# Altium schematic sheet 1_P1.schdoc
size 309 x 223 mm; Symbol: Sheet-Symbol_A4; Device: Sheet-Symbol_A4; Company: 嘉立创EDA; Version: V1.0; Page Size: A4; @Project Name: 电动车中控1; @Page Count: 11; @Update Date: 2024-10-22; @Create Date: 2024-09-26; @Schematic Name: SCH; @Page No: 1; @Page Name: P1; Title Block Position: 3; Width: 1170; Height: 825; Region Start: 1; X Region Count: 6; Y Region Count: 4; Blade Width: 10; @Board Name: STM32F103C8T6; @Create Time: 02:39:01; @Update Time: 14:42:37
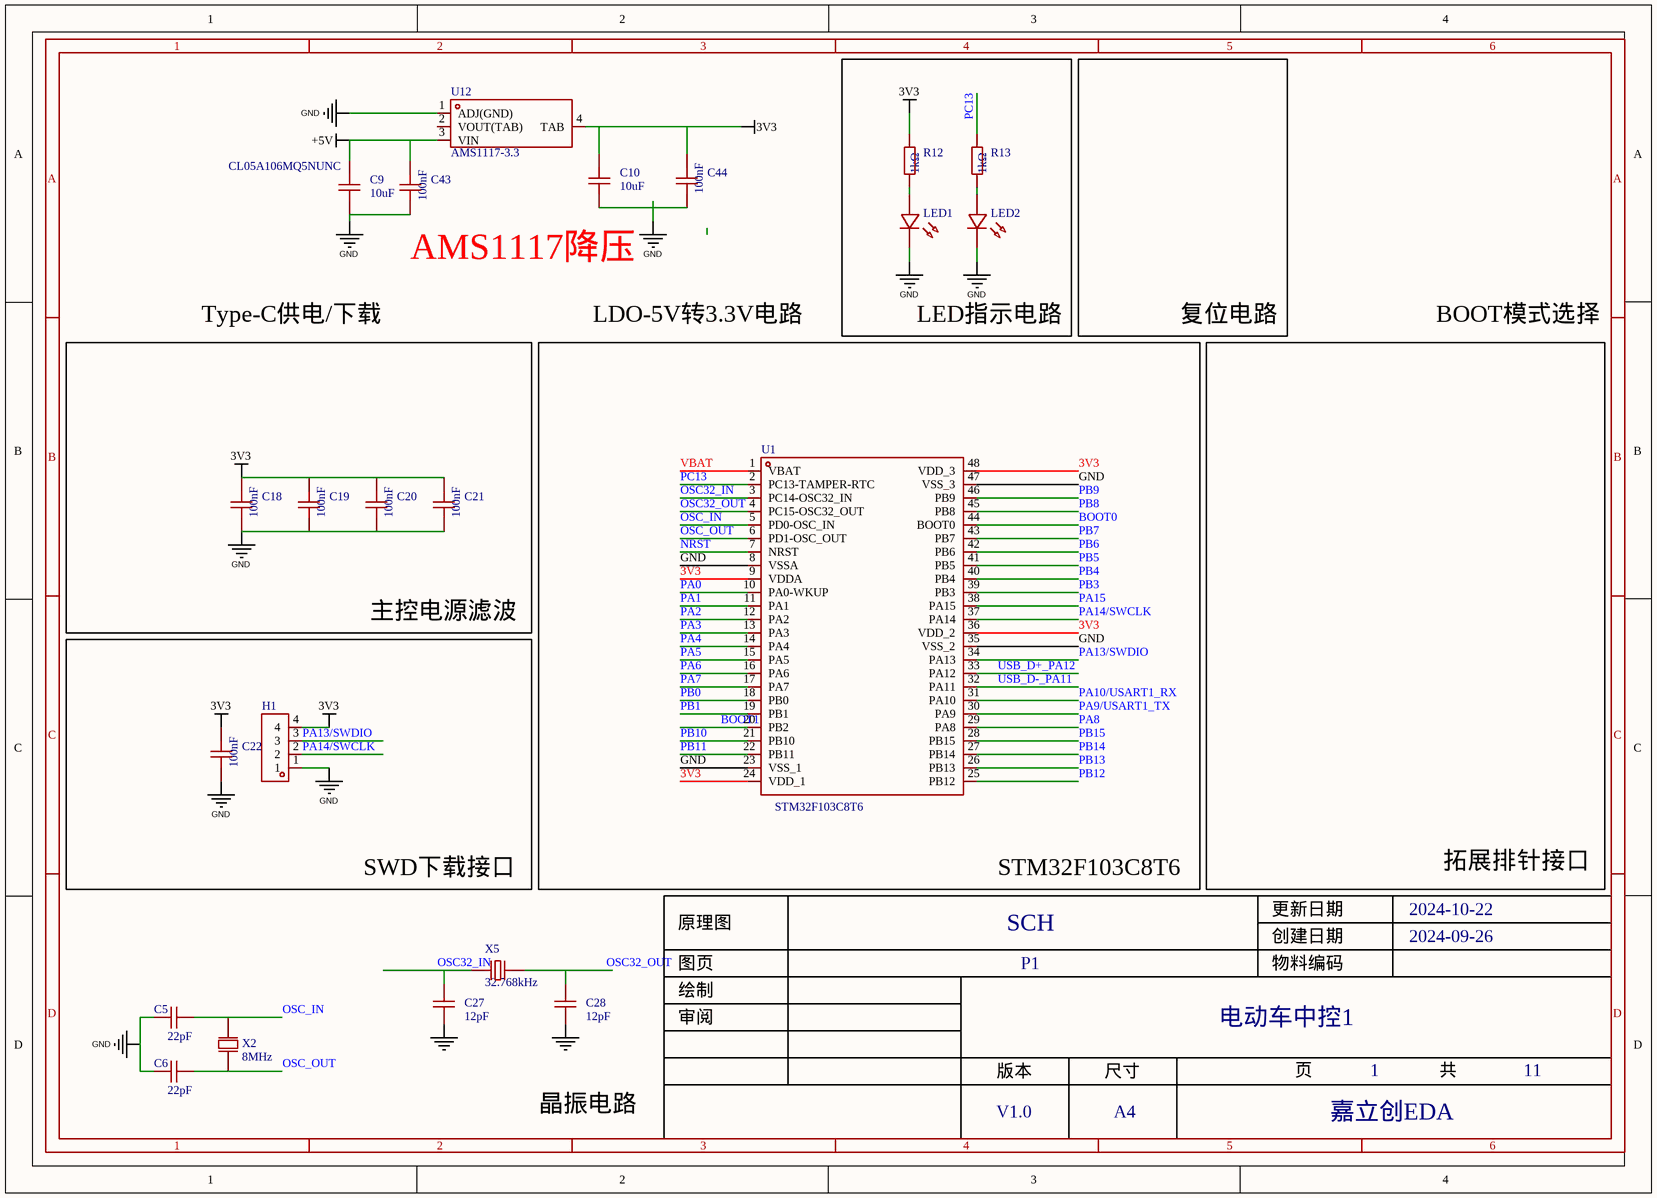
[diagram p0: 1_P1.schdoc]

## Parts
C5  22pF  [C0603]  (value not drawn)
C6  22pF  [C0603]  (value not drawn)
C9  10uF  [C0402]  (value not drawn)
C10  10uF  [C0402]  (value not drawn)
C18  100nF  [C0805]
C19  100nF  [C0805]
C20  100nF  [C0805]
C21  100nF  [C0805]
C22  100nF  [C0805]
C27  12pF  [C0805]
C28  12pF  [C0805]
C43  100nF  [C0805]
C44  100nF  [C0805]
H1  HDR-M_2.54_1x4P  [HDR-TH_4P-P2.54-V-M]  (value not drawn)
LED1  NCD0805R1  [LED0805-R-RD]  (value not drawn)
LED2  KT-0805G  [LED0805-R-RD]  (value not drawn)
R12  1kΩ  [R0805]
R13  1kΩ  [R0805]
U1  STM32F103C8T6  [LQFP-48_L7.0-W7.0-P0.50-LS9.0-BL]
U12  AMS1117-3.3  [SOT-223-3_L6.5-W3.4-P2.30-LS7.0-BR]  (value not drawn)
X2  8MHz  [CRYSTAL-SMD_L11.5-W4.8-LS12.7]  (value not drawn)
X5  32.768kHz  [FC-135R_L3.2-W1.5]

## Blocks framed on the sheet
LED指示电路: LED1 LED2 R12 R13

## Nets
3V3: C10.2 C18.2 C19.2 C20.2 C21.2 C22.2 C44.2 H1.4 R12.2 U1.9(VDDA) U1.24(VDD_1) U1.36(VDD_2) U1.48(VDD_3) U12.4(TAB)
+5V: C9.2 C43.2 U12.3(VIN)
GND: C5.1 C6.1 C9.1 C10.1 C18.1 C19.1 C20.1 C21.1 C22.1 C27.1 C28.1 C43.1 C44.1 H1.1 LED1.1(C) LED2.1(C) U1.8(VSSA) U1.23(VSS_1) U1.35(VSS_2) U1.47(VSS_3) U12.1(ADJ(GND))
BOOT0: U1.44(BOOT0)
BOOT1: U1.20(PB2)
NRST: U1.7(NRST)
OSC32_IN: C27.2 U1.3(PC14-OSC32_IN) X5.1
OSC32_OUT: C28.2 U1.4(PC15-OSC32_OUT) X5.2
OSC_IN: C5.2 U1.5(PD0-OSC_IN) X2.2
OSC_OUT: C6.2 U1.6(PD1-OSC_OUT) X2.1
PA0: U1.10(PA0-WKUP)
PA1: U1.11(PA1)
PA2: U1.12(PA2)
PA3: U1.13(PA3)
PA4: U1.14(PA4)
PA5: U1.15(PA5)
PA6: U1.16(PA6)
PA7: U1.17(PA7)
PA8: U1.29(PA8)
PA9/USART1_TX: U1.30(PA9)
PA10/USART1_RX: U1.31(PA10)
PA13/SWDIO: H1.3 U1.34(PA13)
PA14/SWCLK: H1.2 U1.37(PA14)
PA15: U1.38(PA15)
PB0: U1.18(PB0)
PB1: U1.19(PB1)
PB3: U1.39(PB3)
PB4: U1.40(PB4)
PB5: U1.41(PB5)
PB6: U1.42(PB6)
PB7: U1.43(PB7)
PB8: U1.45(PB8)
PB9: U1.46(PB9)
PB10: U1.21(PB10)
PB11: U1.22(PB11)
PB12: U1.25(PB12)
PB13: U1.26(PB13)
PB14: U1.27(PB14)
PB15: U1.28(PB15)
PC13: R13.2 U1.2(PC13-TAMPER-RTC)
USB_D+_PA12: U1.33(PA12)
USB_D-_PA11: U1.32(PA11)
VBAT: U1.1(VBAT)
NetLED1_2: LED1.2(A) R12.1
NetLED2_2: LED2.2(A) R13.1

Not connected (* = marked no-connect by the designer): U12 2(VOUT(TAB))

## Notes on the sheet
- AMS1117降压
- Type-C供电/下载
- LDO-5V转3.3V电路
- 复位电路
- BOOT模式选择
- 主控电源滤波
- SWD下载接口
- STM32F103C8T6
- 拓展排针接口
- 晶振电路

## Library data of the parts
C5 C6 = CL10C220JB8NNNC: 容值:22pF;精度:±5%;额定电压:50V;材质(温度系数):C0G;; Manufacturer: SAMSUNG(三星); Symbol: CC0603JRNPO9BN220; Add into BOM: yes; Tolerance: ±5%; Voltage Rated: 50V; Temperature Coefficient: C0G
C9 C10 = CL05A106MQ5NUNC: 容值:10uF;精度:±20%;额定电压:6.3V;材质(温度系数):X5R;; Manufacturer: SAMSUNG(三星); Symbol: CL10A106KP8NNNC; Add into BOM: yes; Tolerance: ±20%; Voltage Rated: 6.3V; Temperature Coefficient: X5R
C18-C22 C43 C44 = CC0805KRX7R9BB104: 容值:100nF;精度:±10%;额定电压:50V;材质(温度系数):X7R;; Manufacturer: YAGEO(国巨); Symbol: GRM155R71H104KE14D; Add into BOM: yes; Tolerance: ±10%; Voltage Rated: 50V; Temperature Coefficient: X7R
C27 C28 = 0805CG120J500NT: 容值:12pF;精度:±5%;额定电压:50V;材质(温度系数):C0G;; Manufacturer: FH(风华); Symbol: 0402CG120J500NT; Add into BOM: yes; Tolerance: ±5%; Voltage Rated: 50V; Temperature Coefficient: C0G
H1 = HDR-M_2.54_1x4P: Symbol: PZ254V-11-04P; Convert to PCB: yes
LED1 = NCD0805R1: 灯头类型:-;发光颜色:红色;正向电压(VF):1.6V~2.6V;功率:65mW;正向电流:20mA;主波长:615nm~630nm;二极管配置:独立二极管;透镜颜色:无色透明透镜;色温:-;发光强度:67mcd~195mcd;发光角度:130°;载带方式:-;工作温度:-30℃~+85℃;; Manufacturer: 国星光电; Symbol: LED_R; Convert to PCB: yes; Emitted Color: 红色; Power Dissipation: 65mW; Forward Current: 20mA; Diode Configuration: 独立二极管; Lens Color: 无色透明透镜; Viewing Angle: 130°
LED2 = KT-0805G: 灯头类型:-;发光颜色:翠绿色;正向电压(VF):-;功率:-;正向电流:-;主波长:-;二极管配置:-;透镜颜色:-;色温:-;发光强度:-;发光角度:-;载带方式:-;工作温度:-;; Manufacturer: KENTO; Symbol: LED_B; Convert to PCB: yes; Emitted Color: 翠绿色
R12 R13 = 0805W8F1001T5E: 电阻类型:厚膜电阻;阻值:1kΩ;精度:±1%;功率:125mW;最大工作电压:150V;温度系数:±100ppm/℃;; Manufacturer: UNI-ROYAL(厚声); Symbol: 0402WGF1001TCE; Add into BOM: yes; Tolerance: ±1%; Power(Watts): 125mW; Overload Voltage (Max): 150V
U1 = STM32F103C8T6: CPU内核:ARM-M3;程序存储容量:64KB;RAM总容量:20KB;GPIO端口数量:37;工作电压范围:2V~3.6V;CPU最大主频:72MHz;程序存储器类型:FLASH;; Manufacturer: ST(意法半导体); Add into BOM: yes; CPU Core: ARM-M3; Program Storage Size: 64KB; RAM Size: 20KB; GPIO Ports Number: 37; CPU Maximum Speed: 72MHz; Program Memory Type: FLASH; ADC (Bit): 12bit; Universal Serial Bus: 有; Peripheral/Function: 看门狗；DMA；看门狗；温度传感器
U12 = AMS1117-3.3_C6186: 输出类型:固定;最大输入电压:-;输出电压:3.3V;最大输出电流:1A;电源纹波抑制比(PSRR):72dB@(120Hz);输出极性:正极;; Manufacturer: AMS; Symbol: AMS1117-3.3_C347222; Add into BOM: yes; Output Type: 固定; Output Voltage: 3.3V; MAX Output Current: 1A; Dropout Voltage: 1.3V@(800mA); Output Polarity: 正极; Number of Outputs: 1
X2 = X49SM8MSD2SC: 晶振类型:贴片晶振;频率:8MHz;常温频差:±20ppm;外接负载电容:20pF;频率稳定度(全温):±30ppm;; Manufacturer: YXC(扬兴晶振); Symbol: S1C80000ZWGAC; Add into BOM: yes; Crystal Type: 贴片晶振; Normal temperature Frequency Tolerance: ±20ppm; External load capacitor: 20pF; Frequency Stability(Full temperature range): ±30ppm; Equivalent Series Resistance (ESR): 60Ω
X5 = Q13FC13500004_C32346: 晶振类型:贴片晶振;频率:32.768kHz;常温频差:±20ppm;外接负载电容:12.5pF;; Manufacturer: EPSON(爱普生); Symbol: X321532768KGD2SI; Add into BOM: yes; Crystal Type: 贴片晶振; Normal temperature Frequency Tolerance: ±20ppm; External load capacitor: 12.5pF; Equivalent Series Resistance (ESR): 70kΩ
